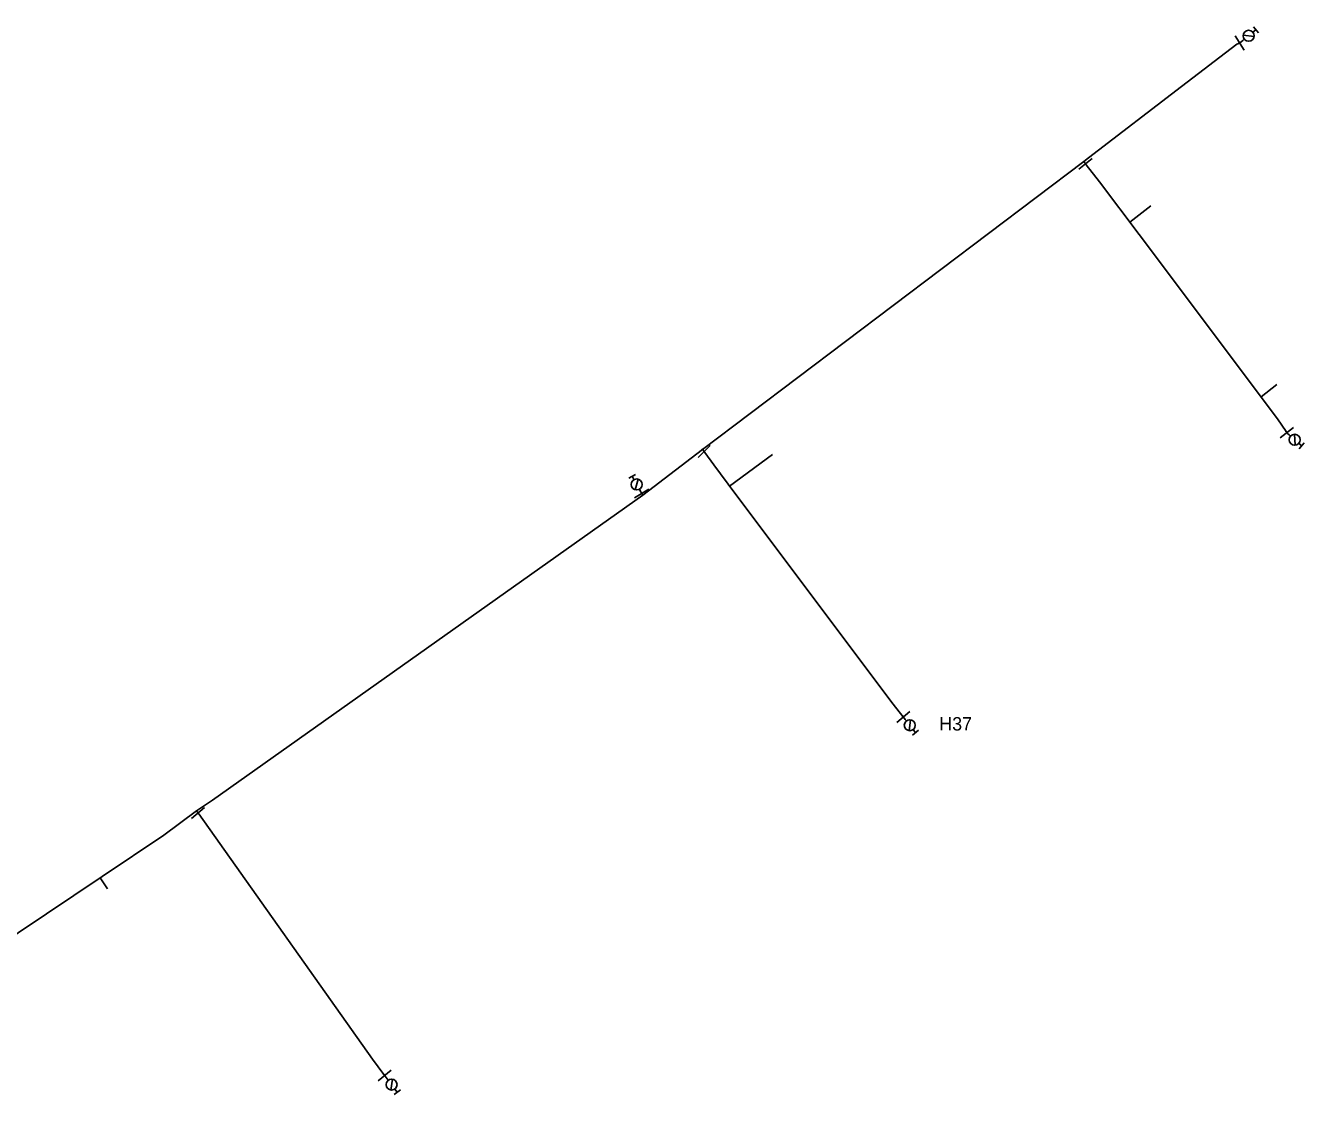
# Model space of a CAD drawing. Extents: x -548873 to -538270, y -1201997 to -1192514.
# Drawn here: x -543619 to -543427.2, y -1197362.8 to -1197202.5 of the extents above; entities that cross this region are included whole.
import ezdxf

# ---------------------------------------------------------------- set-up
doc = ezdxf.new("R2010")
doc.units = 0
for name, color, linetype in [('KN_HRAN_STÁTNÍ', 7, 'Continuous'), ('KN_PARC_Č', 7, 'Continuous'), ('KN_VKP_HRAN_SPORNÁ', 7, 'Continuous'), ('PK_PARC_Čv', 7, 'Continuous'), ('Vrstva 29', 7, 'Continuous')]:
    doc.layers.add(name, color=color, linetype=linetype)

# ---------------------------------------------------------------- blocks, each defined once
blk = doc.blocks.new('160')
at = {"layer": 'KN_HRAN_STÁTNÍ'}
blk.add_circle((0, 0), 0.0458, dxfattribs=at)
blk = doc.blocks.new('147')
at = {"layer": 'KN_HRAN_STÁTNÍ'}
blk.add_line((0, 1.27), (0, -1.27), dxfattribs=at)
blk = doc.blocks.new('133')
at = {"layer": 'KN_HRAN_STÁTNÍ'}
for p, q in [((0.28, 0), (0, 0)), ((0.54, 0.58), (1.7, -0.58)), ((1.94, 0), (2.52, 0)), ((2.52, 0.58), (2.52, -0.58))]:
    blk.add_line(p, q, dxfattribs=at)
blk.add_circle((1.11, 0), 0.825, dxfattribs=at)
blk = doc.blocks.new('150')
at = {"layer": 'KN_HRAN_STÁTNÍ'}
blk.add_line((0, 1.27), (0, -1.27), dxfattribs=at)

msp = doc.modelspace()

# ---------------------------------------------------------------- linework, layer by layer
at = {"layer": 'KN_PARC_Č'}
for points in [[(-543453.487, -1197231.965), (-543450.341, -1197229.494)], [(-543433.829, -1197258.139), (-543431.462, -1197256.296)], [(-543513.494, -1197271.508), (-543507.058, -1197266.756)], [(-543607.852, -1197330.241), (-543606.717, -1197331.887)]]:
    msp.add_lwpolyline(points, dxfattribs=at)
at = {"layer": 'KN_VKP_HRAN_SPORNÁ'}
for points in [[(-543460.41, -1197222.87), (-543459.71, -1197222.29), (-543445.79, -1197211.6), (-543437.48, -1197205.28)], [(-543517.58, -1197266.02), (-543460.41, -1197222.87)], [(-543460.41, -1197222.87), (-543460.16, -1197223.22)], [(-543460.16, -1197223.22), (-543460.06, -1197223.33), (-543458.05, -1197225.89), (-543452.104, -1197233.806), (-543431.38, -1197261.4), (-543430.091, -1197263.333)], [(-543593.401, -1197320.2), (-543591, -1197318.58), (-543526.52, -1197272.86), (-543517.58, -1197266.02)], [(-543517.58, -1197266.02), (-543517.33, -1197266.34)], [(-543517.33, -1197266.34), (-543517.19, -1197266.45), (-543515.88, -1197268.33), (-543512.711, -1197272.55), (-543488.96, -1197304.18), (-543487.54, -1197306.02)], [(-543643.27, -1197344.82), (-543639.06, -1197350.11), (-543636.91, -1197349.99), (-543620.13, -1197338.49), (-543607.541, -1197330.032), (-543598.28, -1197323.81), (-543593.401, -1197320.2)], [(-543593.401, -1197320.2), (-543593.16, -1197320.52)], [(-543593.16, -1197320.52), (-543593.07, -1197320.62), (-543567.03, -1197357.43), (-543565.32, -1197359.701)]]:
    msp.add_lwpolyline(points, dxfattribs=at)
at = {"layer": 'PK_PARC_Čv'}
for points in [[(-543437.48, -1197205.28), (-543437.05, -1197205.09), (-543436.57, -1197204.71)], [(-543430.091, -1197263.333), (-543429.98, -1197263.5), (-543429.9, -1197263.6), (-543429.64, -1197263.83)], [(-543526.52, -1197272.86), (-543526.67, -1197272.63), (-543526.887, -1197272.236)], [(-543487.54, -1197306.02), (-543487.45, -1197306.12), (-543487.17, -1197306.48)], [(-543565.32, -1197359.701), (-543565.2, -1197359.86), (-543565.1, -1197359.97), (-543564.83, -1197360.33)]]:
    msp.add_lwpolyline(points, dxfattribs=at)

# ---------------------------------------------------------------- block references
for name, p, xscale, yscale, rotation in [('150', (-543437.05, -1197205.09), 0.9999999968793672, 0.9999999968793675, 32.00000027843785), ('133', (-543436.57, -1197204.71), 1.000000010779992, 1.0000000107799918, 38.9999989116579), ('150', (-543429.98, -1197263.5), 0.9999999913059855, 0.9999999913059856, -52.999998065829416), ('133', (-543429.64, -1197263.83), 1.0000000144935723, 1.0000000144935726, -40.99999910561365), ('133', (-543526.887, -1197272.236), 1.0000000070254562, 1.0000000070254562, 118.99999892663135), ('150', (-543526.67, -1197272.63), 1.0000000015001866, 1.0000000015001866, -59.00000017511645), ('150', (-543487.45, -1197306.12), 1.0000000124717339, 1.0000000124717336, -49.99999868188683), ('133', (-543487.17, -1197306.48), 1.000000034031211, 1.0000000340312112, -51.999999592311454), ('150', (-543565.2, -1197359.86), 1.0000000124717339, 1.0000000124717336, -49.99999868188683), ('133', (-543564.83, -1197360.33), 0.9999999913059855, 0.9999999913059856, -52.999998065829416)]:
    msp.add_blockref(name, p, dxfattribs=dict(at, xscale=xscale, yscale=yscale, rotation=rotation))
at = {"layer": 'Vrstva 29'}
for name, p, xscale, yscale, rotation in [('160', (-543437.48, -1197205.28), 1.000000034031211, 1.0000000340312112, 38.000000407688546), ('147', (-543460.16, -1197223.22), 1.000000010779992, 1.0000000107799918, 128.99999891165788), ('160', (-543460.41, -1197222.87), 1.000000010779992, 1.0000000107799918, -141.00000108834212), ('160', (-543430.091, -1197263.333), 0.9999999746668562, 0.999999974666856, 124.00000045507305), ('147', (-543517.33, -1197266.34), 0.999999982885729, 0.9999999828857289, 135), ('160', (-543517.58, -1197266.02), 1.000191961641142, 1.000191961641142, 82.91099886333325), ('160', (-543487.54, -1197306.02), 1.000000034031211, 1.0000000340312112, 128.00000040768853), ('147', (-543593.16, -1197320.52), 1.0000000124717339, 1.0000000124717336, 130.0000013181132), ('160', (-543593.401, -1197320.2), 1.0092050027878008, 1.0092050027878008, 168.88308178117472), ('160', (-543565.32, -1197359.701), 0.9999999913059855, 0.9999999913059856, 127.00000193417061)]:
    msp.add_blockref(name, p, dxfattribs=dict(at, xscale=xscale, yscale=yscale, rotation=rotation))

# ---------------------------------------------------------------- texts
at = {"layer": 'PK_PARC_Čv'}
msp.add_text('H37', height=2, dxfattribs=at).set_placement((-543482.07, -1197308.14))

doc.saveas('drawing.dxf')
